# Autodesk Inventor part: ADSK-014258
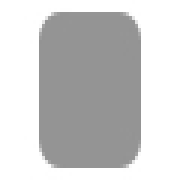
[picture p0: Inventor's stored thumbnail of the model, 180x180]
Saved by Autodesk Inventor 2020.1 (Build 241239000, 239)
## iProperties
Created: 2019-01
Part Number: ADSK-014258
Material: Stahl, weich
Document SubType Name: Modeling
Designer: lutzd
Language: de-DE
Size Designation: 5 x 89,384472 x 39,384472
Categories: <MemberInstance><Categories><Category DisplayName="Sonstige Bauteile" InternalName="5aa15e00-363f-49f2-933f-16f664388e3f" Mnemonic="OTHER"><Category DisplayName
Mass: 137.332 g
Surface Area: 82.4257 cm^2
Volume: 17.4945 cm^3
Density: 7.85 g/cm^3
Appearance: Semi-Polished(8)
IsCustomPart: 1
Title: end cap
Author: lutzd
Revision Number: -
Dimensions: 39,4x89,4x5 mm
Mass: 0,137 kg
DocNumber: ADSK-014258
Folder: 01 - Themengebiete\Simplification\01 - Packaging machine\ADSK-014200\Frame\
VDS_Category: 3D Komponenten
VDS_NumSchm: Autodesk
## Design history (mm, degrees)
sketch "Sketch1"
  geometry: L1 (0, 20.175)-(0, -21.446); L2 (-20.203, 0)-(20.169, 0); L3 (-19.692, 44.692)-(19.692, 44.692); L4 (19.692, 44.692)-(19.692, -44.692); L5 (19.692, -44.692)-(-19.692, -44.692); L6 (-19.692, -44.692)-(-19.692, 44.692); 1 further point
  constraints: 12 end point, 2 horizontal, 2 parallel, 2 point on line, 1 perpendicular, 1 vertical
  dimensions: "d0" = 89.38447 distance between parallel lines of L5 L3 (= height); "d1" = 44.69224 distance between parallel lines of L2 L3 (= 0.5 x height); "d2" = 39.38447 distance between parallel lines of L6 L4 (= width); "d3" = 19.69224 distance between parallel lines of L6 L1 (= 0.5 x width)
extrude "Extrusion1" new body sketch "Sketch1" distance "d4" = 5 (= thickness); taper "d5" = 0 deg
fillet "Fillet1" dims "d6" = 5 (= fillet), "d7" = 0, "fillet" = 5 [user parameter; used in 1 equation term]
chamfer "Chamfer1" distance "d8" = 0 (computed from chamfer); stored, may be unused: second distance "d9" = 2, angle "d10" = 45 deg; dims "d11" = 0, "chamfer" = 0 [user parameter; used in 1 equation term]
body "Solid1"
other parameters: "thickness" = 5 [user parameter; used in 1 equation term], "width" = 39.38447 [user parameter; used in 2 equation terms], "height" = 89.38447 [user parameter; used in 2 equation terms]
